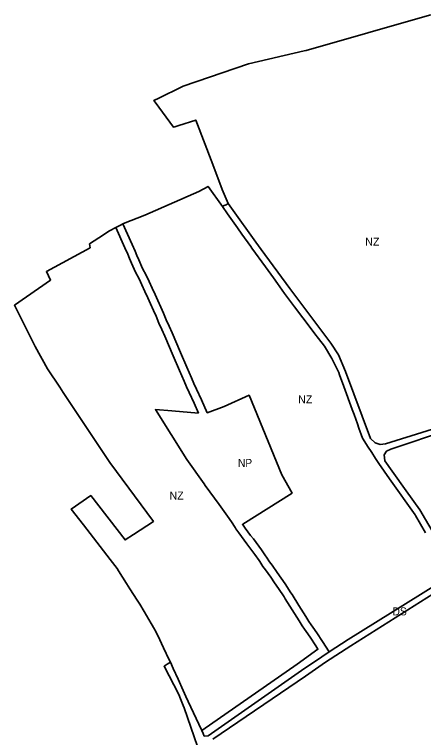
# Model space of a CAD drawing. Extents: x -650451 to -642268, y -1075216 to -1066610.
# Drawn here: x -649748 to -648982, y -1068079 to -1066723 of the extents above; entities that cross this region are included whole.
import ezdxf

# ---------------------------------------------------------------- set-up
doc = ezdxf.new("R2010")
doc.units = 0
doc.header["$LTSCALE"] = 6
doc.layers.add('1', color=7, linetype='Continuous', lineweight=35)
doc.layers.add('2', color=7, linetype='Continuous')
doc.layers.add('3', color=7, linetype='Continuous')

msp = doc.modelspace()

# ---------------------------------------------------------------- linework, layer by layer
at = {"layer": '1'}
for p, q in [((-649472.327, -1067313.644), (-649466.703, -1067326.24)), ((-649425.804, -1067421.21), (-649421.071, -1067431.944)), ((-649403.34, -1067470.579), (-649453.39, -1067466.13)), ((-649393.23, -1067603.28), (-649391.04, -1067606.27)), ((-649298.02, -1067735.58), (-649290.15, -1067746.92)), ((-649253.98, -1067799.2), (-649243.37, -1067815.17)), ((-649228.27, -1067839.26), (-649215.32, -1067859.99)), ((-649215.32, -1067859.99), (-649209.39, -1067869.34)), ((-649209.39, -1067869.34), (-649204.87, -1067875.85)), ((-649450.93, -1067949.05), (-649456.24, -1067937.25)), ((-649441.79, -1067969.38), (-649450.93, -1067949.05)), ((-649219.088, -1067940.964), (-649397.466, -1068065.442)), ((-649432.34, -1067990.39), (-649441.79, -1067969.38)), ((-649427.31, -1068001.57), (-649432.34, -1067990.39)), ((-649397.466, -1068065.442), (-649402.99, -1068053.69))]:
    msp.add_line(p, q, dxfattribs=at)
for points in [[(-649347.85, -1067077.78), (-649359.18, -1067051.27), (-649377.05, -1067004.35), (-649408.78, -1066921.05), (-649440.34, -1066931.29), (-649448.16, -1066933.83), (-649450.37, -1066934.55), (-649484.59, -1066887.67), (-649486.96, -1066884.42), (-649484.88, -1066883.39), (-649480.52, -1066881.24), (-649432.38, -1066857.48), (-649309.81, -1066815.43), (-649206.01, -1066791.34), (-649202.23, -1066790.46), (-648970.96, -1066724.73), (-648965.39, -1066723.15)], [(-649545.203, -1067115.647), (-649544.16, -1067115.09), (-649504.26, -1067099.33), (-649403.08, -1067054.79), (-649385.73, -1067045.47), (-649358.95, -1067083.25)], [(-649347.85, -1067077.78), (-649349.99, -1067078.84), (-649351.87, -1067079.76), (-649355.57, -1067081.58), (-649358.95, -1067083.25)], [(-649347.85, -1067077.78), (-649341.72, -1067086.34), (-649296.02, -1067150.21), (-649286.18, -1067163.62), (-649232.55, -1067236.73), (-649155.84, -1067339.24), (-649141.36, -1067361.14), (-649128.54, -1067392.42), (-649081.51, -1067517.84), (-649073.12, -1067526.28), (-649063.49, -1067529.27), (-649053.79, -1067527.97), (-648829.54, -1067458.42)], [(-649358.95, -1067083.25), (-649349.04, -1067097.21), (-649330.45, -1067123.44), (-649322.28, -1067134.96), (-649305.72, -1067158.32), (-649303.71, -1067161.1), (-649278.24, -1067196.45), (-649263.28, -1067217.2), (-649255.97, -1067227.33), (-649242.45, -1067246.08), (-649223.7, -1067271.04), (-649192.72, -1067312.27), (-649185.7, -1067321.62), (-649178.82, -1067330.78), (-649167.95, -1067345.24), (-649154.11, -1067368.12), (-649140.99, -1067394.43), (-649139.36, -1067398.92), (-649131.44, -1067420.68), (-649115.87, -1067463.47), (-649112.33, -1067473.21), (-649106.04, -1067490.49), (-649103.13, -1067498.5), (-649096.29, -1067517.3), (-649089.24, -1067529.37), (-649087.32, -1067532.31), (-649079.32, -1067544.57), (-649072.12, -1067555.46), (-649065.72, -1067565.13), (-649045.77, -1067593.56), (-648998.24, -1067661.28), (-648997.32, -1067662.6), (-648978.53, -1067694.76)], [(-649456.24, -1067937.25), (-649458.27, -1067933.03), (-649469.14, -1067910.4), (-649480.04, -1067887.69), (-649485.13, -1067877.09), (-649485.91, -1067875.74), (-649492.19, -1067864.93), (-649505.41, -1067842.16), (-649513.19, -1067828.77), (-649518.25, -1067820.92), (-649531.93, -1067799.68), (-649538.12, -1067790.06), (-649553.44, -1067766.28), (-649556.18, -1067762.02), (-649569.12, -1067745.16), (-649619.17, -1067679.93), (-649641.76, -1067650.46), (-649605.24, -1067625.23), (-649541.04, -1067708.33), (-649525.16, -1067697.87), (-649488.04, -1067673.44), (-649569.67, -1067563.37), (-649656.86, -1067431.78), (-649663.47, -1067421.79), (-649686.19, -1067387.51), (-649709.26, -1067345.83), (-649734.42, -1067295.72), (-649748.13, -1067268.42), (-649680.46, -1067221.12), (-649688.23, -1067205.17), (-649606.41, -1067160.45), (-649607.82, -1067153.24), (-649590.2, -1067141.88), (-649570.18, -1067128.98), (-649558.469, -1067122.73)], [(-649545.203, -1067115.647), (-649549.7, -1067118.05), (-649558.469, -1067122.73)], [(-649558.469, -1067122.73), (-649541.537, -1067160.722), (-649536.075, -1067172.622), (-649532.831, -1067180.855), (-649529.013, -1067189.389), (-649521.663, -1067206.124), (-649514.869, -1067218.957)], [(-649159.179, -1067918.309), (-649171.389, -1067898.756), (-649182.332, -1067882.285), (-649189.614, -1067871.638), (-649192.493, -1067867.375), (-649196.89, -1067861.042), (-649202.625, -1067852), (-649215.571, -1067831.276), (-649228.486, -1067810.867), (-649230.661, -1067807.193), (-649241.584, -1067790.752), (-649249.085, -1067780.02), (-649256.092, -1067769.48), (-649265.941, -1067755.582), (-649270.491, -1067749.283), (-649276.322, -1067740.385), (-649277.961, -1067738.175), (-649285.826, -1067726.842), (-649300.936, -1067706.414), (-649306.005, -1067699.828), (-649316.244, -1067685.919), (-649321.3, -1067679), (-649320.47, -1067678.44), (-649228.52, -1067620.294), (-649247.518, -1067586.255), (-649308.75, -1067437.11), (-649355.44, -1067457.94), (-649387.17, -1067469.893), (-649398.28, -1067445.49), (-649407.4, -1067425.77), (-649412.1, -1067415.11), (-649416.8, -1067404.65), (-649425.49, -1067384.46), (-649437.27, -1067357.17), (-649452.95, -1067320.25), (-649458.63, -1067307.53), (-649463.9, -1067295.72), (-649469.21, -1067282.94), (-649474.15, -1067272.12), (-649479.85, -1067259.45), (-649484.93, -1067248.19), (-649490.53, -1067236.1), (-649495.8, -1067223.89), (-649501.49, -1067212.17), (-649508.15, -1067199.59), (-649515.3, -1067183.31), (-649519, -1067175.04), (-649522.27, -1067166.74), (-649527.87, -1067154.54), (-649545.203, -1067115.647)], [(-649514.869, -1067218.957), (-649509.44, -1067230.141), (-649504.224, -1067242.225), (-649498.572, -1067254.427), (-649493.526, -1067265.611), (-649487.812, -1067278.312), (-649482.963, -1067288.934), (-649477.677, -1067301.655), (-649472.327, -1067313.644)], [(-649466.703, -1067326.24), (-649451.059, -1067363.074), (-649439.265, -1067390.397), (-649430.531, -1067410.689), (-649425.804, -1067421.21)], [(-649421.071, -1067431.944), (-649411.913, -1067451.746), (-649403.34, -1067470.579)], [(-649453.39, -1067466.13), (-649484.28, -1067463.88), (-649425.69, -1067557.7), (-649393.23, -1067603.28)], [(-648827.86, -1067465.86), (-649043.58, -1067537.95), (-649051.36, -1067541.81), (-649056.25, -1067548.45), (-649054.62, -1067560), (-649040.88, -1067579.35), (-649014.81, -1067616.11), (-648989.29, -1067652.07), (-648961.65, -1067698.67), (-648935.54, -1067742.7), (-648929.93, -1067752.22), (-648926.79, -1067763.65), (-648926.42, -1067773.69), (-648933.16, -1067786.77), (-648940.02, -1067793.41), (-648952.15, -1067802.08), (-649118.66, -1067906.86), (-649165.63, -1067937.14), (-649203.19, -1067963.4), (-649376.467, -1068081.552)], [(-649391.04, -1067606.27), (-649382.53, -1067618.33), (-649364.69, -1067641.98)], [(-649364.69, -1067641.98), (-649355.46, -1067654.85), (-649349.12, -1067663.84), (-649341.81, -1067674.33), (-649335.26, -1067685.21), (-649333.74, -1067687.4)], [(-649333.74, -1067687.4), (-649328.34, -1067694.79), (-649317.99, -1067708.85), (-649312.91, -1067715.45), (-649298.02, -1067735.58)], [(-649290.15, -1067746.92), (-649288.63, -1067748.97), (-649282.85, -1067757.79)], [(-649282.85, -1067757.79), (-649278.14, -1067764.31), (-649268.46, -1067777.97), (-649261.48, -1067788.47), (-649253.98, -1067799.2)], [(-648959.69, -1067793.21), (-649123.43, -1067894.75), (-649159.179, -1067918.309)], [(-649243.37, -1067815.17), (-649241.28, -1067818.7), (-649228.27, -1067839.26)], [(-649204.87, -1067875.85), (-649202.02, -1067880.07), (-649194.77, -1067890.67), (-649184, -1067906.88)], [(-649184, -1067906.88), (-649179.96, -1067913.35), (-649219.088, -1067940.964)], [(-649159.179, -1067918.309), (-649172.99, -1067927.41), (-649210.54, -1067953.29), (-649385.41, -1068075.32), (-649392.88, -1068075.9), (-649394.83, -1068071.05), (-649397.466, -1068065.442)], [(-649456.24, -1067937.25), (-649459.13, -1067939.2), (-649462.36, -1067941.37), (-649467.89, -1067945.1), (-649440.52, -1067998.08), (-649437.23, -1068006.17), (-649432.13, -1068018.42), (-649430.62, -1068023.16), (-649405.33, -1068095.73), (-649363.01, -1068217.61)], [(-649402.99, -1068053.69), (-649423.04, -1068011.05), (-649427.31, -1068001.57)]]:
    msp.add_lwpolyline(points, dxfattribs=at)

# ---------------------------------------------------------------- texts
at = {"layer": '2'}
for p in [(-649091.517, -1067156.674), (-649217.127, -1067452.228), (-649458.004, -1067632.516)]:
    msp.add_text('NZ', height=15, dxfattribs=at).set_placement(p)
at = {"layer": '2', "width": 0.95}
msp.add_text('DS', height=15, dxfattribs=at).set_placement((-649040.197, -1067849.728))
at = {"layer": '3', "width": 0.95}
msp.add_text('NP', height=15, dxfattribs=at).set_placement((-649329.654, -1067571.355))

doc.saveas('drawing.dxf')
